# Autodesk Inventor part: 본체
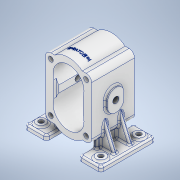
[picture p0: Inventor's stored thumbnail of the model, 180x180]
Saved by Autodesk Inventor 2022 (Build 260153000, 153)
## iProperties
Created: 2023-06
Part Number: 본체
Material: 알루미늄 6061
Document SubType Name: Modeling
Designer: PC-01
Density: 2.7 g/cm^3
Appearance: 알루미늄 - 평지
Mass: 1267.13 g
Surface Area: 985.949 cm^2
Volume: 469.308 cm^3
Author: PC-01
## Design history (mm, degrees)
sketch "스케치1"
  geometry: L1 (42.5, -55)-(-42.5, -55); L2 (-42.5, -55)-(-42.5, 55); L3 (-42.5, 55)-(42.5, 55); L4 (42.5, 55)-(42.5, -55); L5 (42.5, -55)-(-42.5, 55); L6 (-42.5, -55)-(42.5, 55); L7 (0, 24)-(0, -24); A1 r 40 centre (0, 24) between (25.278, 55) and (-25.278, 55); A2 r 40 centre (0, -24) between (-25.278, -55) and (25.278, -55); 2 further points
  constraints: 14 end point, 4 midpoint, 4 point on circle, 4 point on line, 2 centre point, 2 coincident, 2 parallel, 1 horizontal, 1 perpendicular, 1 vertical
  dimensions: "d0" = 110 distance of L1.end L2.end; "d1" = 85 distance of L2.end L3.end; "d2" = 48 distance of L7.start L7.end; "d3" = 80 diameter of A1; "d4" = 80 diameter of A2
extrude "돌출1" new body sketch "스케치1" stored distance "d5" = 79; taper "d6" = 0 deg
sketch "스케치2"
  geometry: L1 (-42.5, 55)-(-25.278, 55) reference; L2 (25.278, 55)-(42.5, 55) reference; L3 (42.5, 55)-(42.5, -55) reference; L4 (42.5, -55)-(25.278, -55) reference; L5 (-25.278, -55)-(-42.5, -55) reference; L6 (-42.5, -55)-(-42.5, 55) reference; L7 (-22.5, 6.507)-(-22.5, -6.507); L8 (22.5, 6.507)-(22.5, -6.507); A1 r 40 centre (0, 24) between (25.278, 55) and (-25.278, 55) reference; A2 r 40 centre (0, -24) between (-25.278, -55) and (25.278, -55) reference; A3 r 28.5 centre (0, 24) between (22.5, 6.507) and (-22.5, 6.507); A4 r 28.5 centre (0, -24) between (-22.5, -6.507) and (22.5, -6.507); 1 further point
  constraints: 4 end point, 4 point on circle, 2 centre point, 2 coincident, 2 parallel, 1 vertical
  dimensions: "d8" = 57 diameter of A3; "d9" = 57 diameter of A4; "d10" = 45 distance between parallel lines of L8 L7
extrude "돌출2" cut sketch "스케치2" stored distance "d11" = 79; taper "d12" = 0 deg
fillet "모깎기1" dims "d13" = 10
node "작업 평면1"
sketch "스케치3"
  geometry: L1 (-30, -50)-(-70, -50); L2 (-70, -50)-(-70, 50); L3 (-70, 50)-(-30, 50); L4 (-30, 50)-(-30, -50); 2 further points
  constraints: 8 end point, 2 parallel, 1 horizontal, 1 horizontal alignment, 1 midpoint, 1 perpendicular
  dimensions: "d15" = 40 distance of L2.end L3.end; "d16" = 100 distance of L1.end L2.end; "d17" = 70 distance from line of L2 point (0, 0)
extrude "돌출3" join sketch "스케치3" distance "d18" = 9; taper "d19" = 0 deg
sketch "스케치4"
  geometry: L1 (-32.5, -55)-(-25.278, -55) reference; L2 (25.278, -55)-(32.5, -55) reference; L3 (42.5, -45)-(42.5, 45) reference; L4 (32.5, 55)-(25.278, 55) reference; L5 (-25.278, 55)-(-32.5, 55) reference; L6 (-42.5, 45)-(-42.5, -45) reference; L7 (22.5, 6.507)-(22.5, -6.507) reference; L8 (-22.5, -6.507)-(-22.5, 6.507) reference; C1 r 4.5 at (-32.5, 45); C2 r 4.5 at (32.5, 45); C3 r 4.5 at (32.5, -45); C4 r 4.5 at (-32.5, -45); A1 r 10 centre (-32.5, -45) between (-42.5, -45) and (-32.5, -55) reference; A2 r 40 centre (0, -24) between (-25.278, -55) and (25.278, -55) reference; A3 r 10 centre (32.5, -45) between (32.5, -55) and (42.5, -45) reference; A4 r 10 centre (32.5, 45) between (42.5, 45) and (32.5, 55) reference; A5 r 40 centre (0, 24) between (25.278, 55) and (-25.278, 55) reference; A6 r 10 centre (-32.5, 45) between (-32.5, 55) and (-42.5, 45) reference; A7 r 28.5 centre (0, 24) between (22.5, 6.507) and (-22.5, 6.507) reference; A8 r 28.5 centre (0, -24) between (-22.5, -6.507) and (22.5, -6.507) reference; 1 further point
  constraints: 4 centre point, 4 coincident
  dimensions: "d20" = 9 diameter of C1; "d21" = 9 diameter of C2; "d22" = 9 diameter of C3; "d23" = 9 diameter of C4
extrude "돌출4" cut sketch "스케치4" stored distance "d24" = 9 (= d21); taper "d25" = 0 deg
sketch "스케치5"
  geometry: C1 r 9 at (55, 35); 1 further point
  constraints: 1 centre point
  dimensions: "d26" = 55 horizontal distance of C1.centre point (0, 0); "d27" = 35 vertical distance of C1.centre point (0, 0); "d37" = 18 diameter of C1
extrude "돌출5" join sketch "스케치5" distance "d28" = 3; taper "d29" = 0 deg
sketch "스케치6"
  geometry: C1 r 9 at (0, 0) reference; C2 r 4.5 at (0, 0); 1 further point
  constraints: 1 centre point, 1 coincident
  dimensions: "d30" = 9 diameter of C2
extrude "돌출6" cut sketch "스케치6" stored distance "d31" = 9; taper "d32" = 0 deg
sketch "스케치7"
  geometry: L1 (30, 25)-(38, 25); L2 (38, 25)-(38, -25); L3 (38, -25)-(30, -25); L4 (30, -25)-(30, 25); L5 (30, -50)-(70, -50) reference; L6 (30, 50)-(30, -50) reference; L7 (70, 50)-(30, 50) reference; L8 (70, -50)-(70, 50) reference; C1 r 4.5 at (55, 35) reference; 2 further points
  constraints: 8 end point, 2 midpoint, 2 parallel, 1 horizontal, 1 perpendicular
  dimensions: "d33" = 50 distance of L1.end L2.end; "d34" = 8 distance of L2.end L3.end
extrude "돌출7" join sketch "스케치7" stored distance "d35" = 10; taper "d36" = 0 deg
node "작업 평면2"
sketch "스케치8"
  geometry: L1 (46, -71)-(64, -71) reference; L2 (62, -71)-(42.5, -25.061); L3 (42.5, 45)-(42.5, -45) reference; L4 (70, -80)-(70, -71) reference; 1 further point
  constraints: 2 end point, 2 point on line
  dimensions: "d39" = 23 deg angle of L4 L2; "d40" = 8 distance from line of L4 L2.start
feature "리브1" sketch "스케치8" dims "d41" = 1, "d42" = 7, "d43" = 0, "d44" = 0, "d45" = 1, "d46" = 1
sketch "스케치9"
  geometry: L1 (-39.5, 50)-(-39.5, 40); L2 (-54.5, 50)-(-54.5, 40); L3 (-24.5, 40)-(-24.5, 50); A1 r 15 centre (-39.5, 50) between (-24.5, 50) and (-54.5, 50); A2 r 15 centre (-39.5, 40) between (-54.5, 40) and (-24.5, 40); 2 further points
  constraints: 8 end point, 4 point on circle, 4 tangent, 2 centre point, 1 coincident, 1 midpoint, 1 parallel, 1 vertical
  dimensions: "d47" = 30 distance between parallel lines of L3 L2; "d48" = 10 distance of L1.start L1.end
extrude "돌출8" join sketch "스케치9" distance "d49" = 5; taper "d50" = 0 deg
sketch "스케치10"
  geometry: 2 further points
  constraints: 1 coincident
hole "구멍1" sketch "스케치10" at (-39.5, 45) diameter "d51" = 10.5; stored, may be unused: countersink angle "d57" = 90 deg, drill point angle "d59" = 0 deg; dims "d52" = 11, "d53" = 0.62479, "d54" = 10.589, "d55" = 4, "d56" = 2, "d58" = 25
sketch "스케치11"
  geometry: L1 (-4.5, 30.507)-(0, 30.507); L2 (0, 30.507)-(0, -17.493); L3 (0, -17.493)-(-4.5, -17.493); L4 (-4.5, -17.493)-(-4.5, 30.507); L5 (0, -50.565)-(-79, -50.565) reference; L6 (-79, -50.565)-(-79, -34.986) reference; L7 (-79, -34.986)-(0, -34.986) reference; L8 (0, -34.986)-(0, -50.565) reference; L9 (-79, 13.014)-(0, 13.014) reference; L10 (0, 13.014)-(0, 0) reference; L11 (0, 0)-(-79, 0) reference; L12 (-79, 0)-(-79, 13.014) reference; L13 (-79, 63.579)-(0, 63.579) reference; L14 (0, 63.579)-(0, 48) reference; L15 (0, 48)-(-79, 48) reference; L16 (-79, 48)-(-79, 63.579) reference; C1 r 5.25 at (-39.5, 6.507) reference; 2 further points
  constraints: 8 end point, 2 midpoint, 2 parallel, 1 horizontal, 1 perpendicular
  dimensions: "d60" = 4.5 distance of L1.start L1.end; "d61" = 48 distance of L3.end L1.start
extrude "돌출9" cut sketch "스케치11" distance "d62" = 4.5; taper "d63" = 0 deg
node "작업 평면3"
sketch "스케치13"
  geometry: 2 further points
  constraints: 1 vertical alignment, 1 other
  dimensions: "d67" = 20 distance of point (0, 0) point (0, 20)
feature "엠보싱1" sketch "스케치13" dims "d0" = 110, "d1" = 85, "d2" = 48, "d3" = 80, "d4" = 80, "d68" = 0.5, "d69" = 0
fillet "모깎기2" dims "d70" = 3
fillet "모깎기3" dims "d71" = 3
fillet "모깎기4" dims "d72" = 3
fillet "모깎기5" dims "d73" = 3
fillet "모깎기6" dims "d74" = 5
fillet "모깎기7" dims "d75" = 3
node "솔리드1"
mirror "미러1"
mirror "미러2"
mirror "미러3"
mirror "미러4"
mirror "미러5"
mirror "미러6"
node "투영된 루프1"
node "투영된 루프2"
node "투영된 루프3"
node "투영된 루프4"
node "절단 모서리 투영1"
feature "A9D066F2-1C7D-4E18-AEED-F7BC21143FA4" dims "d51" = 10.5, "d52" = 11, "d53" = 0.62479, "d54" = 10.589, "d55" = 4, "d56" = 2, "d57" = 90 deg, "d58" = 25, "d59" = 0
other parameters: "d38" = -14.5
